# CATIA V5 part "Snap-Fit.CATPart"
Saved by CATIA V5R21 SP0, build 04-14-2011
Part number: Snap-Fit
Bounding box of the stored display mesh (mm): x -11 to 11, y -11 to 11, z -9 to 10
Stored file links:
  C:\Users\zerma\Pictures\Perso\Snap-Fit.CATPart
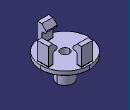
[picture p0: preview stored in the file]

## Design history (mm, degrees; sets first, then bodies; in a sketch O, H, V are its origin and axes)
Body1 (main body)
  Sketch1 on xy-plane, origin (0, 0, 0), H (1, 0, 0), V (0, 1, 0)
    circle A1 centre (0, 0) radius 11
    radius A1 = 11
  Pad1: profile Sketch1, direction (0, 0, 1), length 2
  Sketch2 on end face of Pad1, origin (0, 0, 2), H (1, 0, 0), V (0, 1, 0)
    line L1 (-2.5, -8) -> (2.5, -8)
    line L2 (2.5, -8) -> (2.5, -10)
    line L3 (2.5, -10) -> (-2.5, -10)
    line L4 (-2.5, -10) -> (-2.5, -8)
    distance L3 L1 = 2
    distance L2 L4 = 5
    distance L3 H = 10
    distance L2 V = 2.5
    horizontal: L1 H, L3 H
    vertical: L2 V, L4 V
  Pad2: profile Sketch2, direction (0, 0, 1), length 5
  Sketch3 on end face of Pad2, origin (0, 0, 7), H (1, 0, 0), V (0, 1, 0)
    line L1 (-2.5, -6) -> (2.5, -6)
    line L2 (2.5, -6) -> (2.5, -10)
    line L3 (2.5, -10) -> (-2.5, -10)
    line L4 (-2.5, -10) -> (-2.5, -6)
    reference projected line E1 (2.5, -10) -> (2.5, -8) from edge [face of Pad2 from Sketch2.L2 | end face of Pad2]
    reference projected line E2 (-2.5, -10) -> (2.5, -10) from edge [face of Pad2 from Sketch2.L3 | end face of Pad2]
    reference projected line E3 (-2.5, -8) -> (-2.5, -10) from edge [face of Pad2 from Sketch2.L4 | end face of Pad2]
    length L2 = 4
    horizontal: L1 H, L3 H
    vertical: L2 V, L4 V
    coincidence: L2 E1, L3 E2, L4 E3
  Pad3: profile Sketch3, direction (0, 0, 1), length 3
  Fillet1: radius 1, on edge [face of Pad2 from Sketch2.L1 | start face of Pad3]
  Fillet2: radius 0.5, on edge [start face of Pad3 | face of Pad3 from Sketch3.L1]
  Chamfer1: length 2, angle 45, on edge [face of Pad3 from Sketch3.L1 | end face of Pad3]
  Fillet3: radius 0.1, on edge [end face of Pad1 | face of Pad2 from Sketch2.L1]; edge [end face of Pad1 | face of Pad3] (x3)
  CircPattern1: of Pad1, Pad2, Pad3, Fillet1, Fillet2, Chamfer1, Fillet3, instances 3, angular step 90, axis from end face of Pad1
  Sketch4 on face of CircPattern1, origin (0, 0, 0), H (1, 0, 0), V (0, -1, 0)
    circle A1 centre (0, 0) radius 2
    radius A1 = 2
  Pocket1: profile Sketch4, direction (0, 0, 1), up to face of CircPattern1
  Sketch5 on face of CircPattern1, origin (0, 0, 0), H (1, 0, 0), V (0, -1, 0)
    circle A1 centre (0, 0) radius 2
    circle A2 centre (0, 0) radius 3.5
    radius A1 = 2
    radius A2 = 3.5
  Pad4: profile Sketch5, direction (0, 0, -1), length 9
  Fillet4: radius 0.3, on edge [face of CircPattern1 | face of CircPattern1]
  Fillet5: radius 0.3, on edge [face of CircPattern1 | face of Pad4 from Sketch5.A2]
  CLDGeom1 "Maillage.1"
